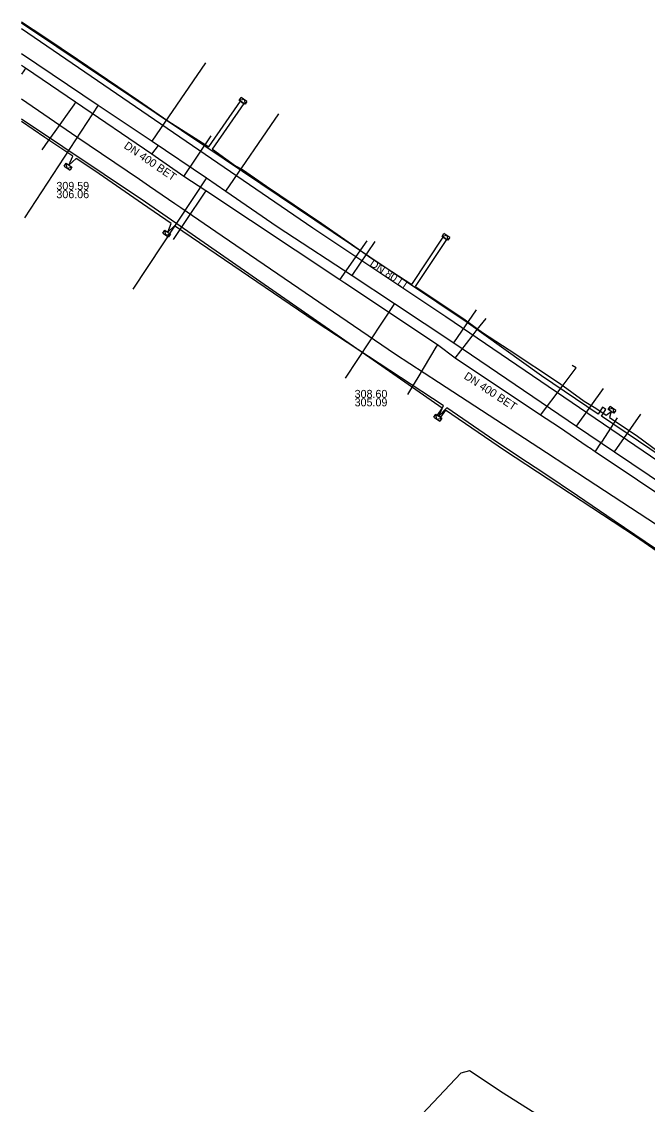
# Model space of a CAD drawing. Extents: x -600391 to -599491, y -1160176 to -1159402.
# Drawn here: x -600391 to -600328.5, y -1160119 to -1160010.7 of the extents above; entities that cross this region are included whole.
import ezdxf

# ---------------------------------------------------------------- set-up
doc = ezdxf.new("R2010")
doc.units = 0
for name, color, linetype in [('31', 7, 'Continuous'), ('Vrstva 12', 7, 'Continuous'), ('Vrstva 13', 7, 'Continuous'), ('Vrstva 15', 7, 'Continuous'), ('Vrstva 19', 7, 'Continuous'), ('Vrstva 42', 7, 'Continuous'), ('Vrstva 43', 7, 'Continuous'), ('Vrstva 55', 7, 'Continuous'), ('Vrstva 9', 7, 'Continuous')]:
    doc.layers.add(name, color=color, linetype=linetype)

# ---------------------------------------------------------------- blocks, each defined once
blk = doc.blocks.new('NN630')
at = {"layer": '31'}
for points in [[(0, -0.7), (-0.7, 0)], [(-0.7, -0.7), (-0.7, 0), (0.7, 0), (0.7, -0.7)], [(-0.7, -0.7), (0.7, -0.7)], [(0, -0.7), (0.7, 0)]]:
    blk.add_lwpolyline(points, dxfattribs=at)

msp = doc.modelspace()

# ---------------------------------------------------------------- linework, layer by layer
at = {"layer": 'Vrstva 13'}
for p, q in [((-600377.97, -1160022.68), (-600372.6, -1160014.84)), ((-600383.38, -1160019.06), (-600390.72, -1160030.32)), ((-600370.61, -1160027.67), (-600365.31, -1160019.93)), ((-600372.54, -1160026.35), (-600379.89, -1160037.46)), ((-600357.97, -1160036.11), (-600355.7, -1160032.7)), ((-600353.75, -1160038.9), (-600358.7, -1160046.37)), ((-600347.83, -1160042.83), (-600345.57, -1160039.55)), ((-600335.57, -1160051.15), (-600332.89, -1160047.4)), ((-600331.77, -1160053.74), (-600329.13, -1160049.95))]:
    msp.add_line(p, q, dxfattribs=at)
for points in [[(-600391.01, -1160013.89), (-600383.38, -1160019.06), (-600377.97, -1160022.68), (-600372.54, -1160026.35), (-600370.61, -1160027.67), (-600365.48, -1160031.2), (-600364.61, -1160031.76)], [(-600364.61, -1160031.76), (-600357.97, -1160036.11), (-600353.75, -1160038.9), (-600347.83, -1160042.83), (-600335.57, -1160051.15), (-600331.77, -1160053.74), (-600316.28, -1160064.17), (-600315.77, -1160064.51), (-600310.16, -1160068.2), (-600292.01, -1160080.31), (-600289.22, -1160082.13), (-600264.27, -1160099.11), (-600257.81, -1160103.36), (-600247.15, -1160101.04), (-600241.8, -1160099.85), (-600232.66, -1160092.61)]]:
    msp.add_lwpolyline(points, dxfattribs=at)
at = {"layer": 'Vrstva 19'}
for points in [[(-600321, -1160062.23), (-600333.71, -1160053.74), (-600334.28, -1160053.33), (-600334.41, -1160053.25), (-600337.36, -1160051.23), (-600339.17, -1160050.08), (-600347.68, -1160044.37), (-600349.47, -1160043.02), (-600358.71, -1160036.86), (-600359.21, -1160036.52), (-600372.62, -1160027.62), (-600374.81, -1160026.21), (-600378.01, -1160023.97), (-600385.63, -1160018.77), (-600390.61, -1160015.38), (-600391.01, -1160015.1)], [(-600390.61, -1160015.38), (-600390.78, -1160015.63), (-600391.01, -1160015.98)], [(-600385.63, -1160018.77), (-600385.81, -1160019.02), (-600387.71, -1160021.71), (-600388.39, -1160022.66), (-600389, -1160023.52)], [(-600374.81, -1160026.21), (-600372.09, -1160022.14)], [(-600378.01, -1160023.97), (-600377.34, -1160023.1)], [(-600372.62, -1160027.62), (-600372.79, -1160027.87), (-600374.6, -1160030.59), (-600375.21, -1160031.51), (-600375.87, -1160032.5)], [(-600359.21, -1160036.52), (-600356.48, -1160032.64)], [(-600347.68, -1160044.37), (-600345.99, -1160042.17), (-600345.48, -1160041.51), (-600344.61, -1160040.39)], [(-600349.47, -1160043.02), (-600349.63, -1160043.28), (-600351.44, -1160046.29), (-600351.97, -1160047.18), (-600352.47, -1160048.01)], [(-600339.17, -1160050.08), (-600337, -1160047.21), (-600335.6, -1160045.35), (-600336, -1160045.09)], [(-600331.5, -1160050.33), (-600333.08, -1160052.78)], [(-600333.71, -1160053.74), (-600333.08, -1160052.78)]]:
    msp.add_lwpolyline(points, dxfattribs=at)
at = {"layer": 'Vrstva 42'}
for points in [[(-600391.01, -1160010.72), (-600388.71, -1160012.27), (-600385.43, -1160014.48), (-600379.32, -1160018.61), (-600376.42, -1160020.63), (-600372.31, -1160023.24), (-600369.15, -1160018.68), (-600368.98, -1160018.79), (-600368.82, -1160018.9), (-600371.97, -1160023.46), (-600371.94, -1160023.48), (-600369.64, -1160025.13), (-600368.95, -1160025.51), (-600366.56, -1160027.16), (-600361.01, -1160030.89), (-600357.96, -1160033.04), (-600356.13, -1160034.32), (-600352.03, -1160036.99), (-600348.88, -1160032.28), (-600348.71, -1160032.39), (-600348.55, -1160032.5), (-600351.69, -1160037.21), (-600351.63, -1160037.25), (-600346.69, -1160040.52), (-600344.98, -1160041.81), (-600342.29, -1160043.55), (-600337.26, -1160046.87), (-600334.8, -1160048.65), (-600333.63, -1160049.38), (-600332.61, -1160050.07), (-600332.12, -1160049.69), (-600332.28, -1160050.29), (-600329.62, -1160052.08), (-600327.32, -1160053.77)], [(-600330.52, -1160051.9), (-600333.08, -1160050.17), (-600332.63, -1160049.51), (-600332.79, -1160049.39), (-600332.96, -1160049.28), (-600333.41, -1160049.95), (-600339.07, -1160046.12), (-600346.6, -1160040.74), (-600352.55, -1160036.74), (-600372.61, -1160023.24), (-600387.48, -1160013.24), (-600391.01, -1160010.87)], [(-600391.01, -1160020.43), (-600378.65, -1160028.72), (-600375.6, -1160030.85)], [(-600313.09, -1160073.25), (-600328.72, -1160062.73), (-600331.81, -1160060.62), (-600335.46, -1160058.13), (-600338.85, -1160055.87), (-600341.33, -1160054.22), (-600344.26, -1160052.26), (-600348.53, -1160049.34), (-600349.33, -1160050.17), (-600348.86, -1160049.11), (-600348.9, -1160049.09), (-600361.68, -1160040.71), (-600375.74, -1160031.12), (-600376.42, -1160031.76), (-600376.07, -1160030.89), (-600378.94, -1160028.94), (-600383.7, -1160025.64), (-600385.56, -1160024.39), (-600386.28, -1160025.08), (-600385.89, -1160024.17), (-600388.71, -1160022.3), (-600391.01, -1160020.69)], [(-600375.6, -1160030.85), (-600354.27, -1160045.68), (-600348.98, -1160049.32), (-600349.48, -1160050.05), (-600349.31, -1160050.17)], [(-600298.08, -1160084.9), (-600298.16, -1160084.84), (-600297.71, -1160084.18), (-600299.55, -1160082.9), (-600305.99, -1160078.53), (-600306.45, -1160079.21), (-600306.61, -1160079.09), (-600306.78, -1160078.98), (-600306.32, -1160078.3), (-600312.66, -1160073.99), (-600329.69, -1160062.21), (-600342.78, -1160053.6), (-600348.65, -1160049.55), (-600349.15, -1160050.28), (-600349.31, -1160050.17)], [(-600283.31, -1160083.83), (-600311.46, -1160064.8), (-600330.52, -1160051.9)]]:
    msp.add_lwpolyline(points, dxfattribs=at)
at = {"layer": 'Vrstva 55'}
for points in [[(-600235.88, -1160090.06), (-600243.77, -1160096.03), (-600246.95, -1160097.03), (-600258.73, -1160101.28), (-600285.65, -1160082.77), (-600317.3, -1160061.42), (-600325.77, -1160055.81), (-600348.64, -1160040.24), (-600361.9, -1160031.37), (-600391.01, -1160011.45)], [(-600331.42, -1160125.14), (-600342.91, -1160117.85), (-600346.26, -1160115.64), (-600347.14, -1160115.85), (-600354.3, -1160123.45)]]:
    msp.add_lwpolyline(points, dxfattribs=at)
at = {"layer": 'Vrstva 9'}
msp.add_line((-600391.01, -1160018.43), (-600385.48, -1160022.23), dxfattribs=at)
for points in [[(-600385.48, -1160022.23), (-600379.25, -1160026.48), (-600378.22, -1160027.18), (-600375.69, -1160028.91), (-600375.11, -1160029.3), (-600370.97, -1160032.13), (-600353.65, -1160043.98)], [(-600353.65, -1160043.98), (-600349.35, -1160046.76), (-600338.57, -1160053.81), (-600334.52, -1160056.46), (-600319.67, -1160066.18), (-600318.62, -1160066.84)]]:
    msp.add_lwpolyline(points, dxfattribs=at)

# ---------------------------------------------------------------- block references
at = {"layer": 'Vrstva 43'}
for p, xscale, yscale, rotation in [((-600368.98, -1160018.79), 0.5, 0.5, 146), ((-600386.27, -1160025.08), 0.49999999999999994, 0.5000000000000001, -34.000000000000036), ((-600376.42, -1160031.76), 0.49999999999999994, 0.5000000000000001, -34.000000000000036), ((-600348.71, -1160032.39), 0.5, 0.5, 147), ((-600332.12, -1160049.69), 0.5, 0.5, 147), ((-600349.33, -1160050.17), 0.5, 0.5, -32.999999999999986)]:
    msp.add_blockref('NN630', p, dxfattribs=dict(at, xscale=xscale, yscale=yscale, rotation=rotation))

# ---------------------------------------------------------------- texts
at = {"layer": 'Vrstva 12'}
for rotation, p in [(325.7265, (-600380.86, -1160023.31)), (326.8151, (-600346.89, -1160046.36))]:
    msp.add_text('DN 400 BET', height=0.8, rotation=rotation, dxfattribs=at).set_placement(p)
for s, p in [('309.59', (-600387.54, -1160027.54)), ('306.06', (-600387.54, -1160028.37)), ('308.60', (-600357.74, -1160048.34)), ('305.09', (-600357.74, -1160049.18))]:
    msp.add_text(s, height=0.8, dxfattribs=at).set_placement(p)
at = {"layer": 'Vrstva 15'}
msp.add_text('DN 80 LI', height=0.8, rotation=326.0703, dxfattribs=at).set_placement((-600356.3, -1160035.09))

doc.saveas('drawing.dxf')
